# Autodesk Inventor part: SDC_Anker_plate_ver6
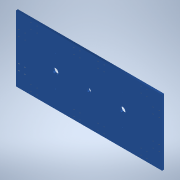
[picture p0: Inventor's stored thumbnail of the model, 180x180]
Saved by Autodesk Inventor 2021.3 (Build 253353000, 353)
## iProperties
Created: 2022-01
Part Number: SDC_Anker_plate_ver6
Material: アルミニウム 6061
Document SubType Name: Modeling
Designer: kengo
Density: 2.7 g/cm^3
Appearance: アルミニウム - フラット
Author: kengo
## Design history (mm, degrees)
sketch "スケッチ1"
  geometry: L1 (-589.671, 316.432)-(590.329, 316.432); L2 (590.329, 316.432)-(590.329, -283.568); L3 (590.329, -283.568)-(-589.671, -283.568); L4 (-589.671, -283.568)-(-589.671, 316.432); 1 further point
  constraints: 8 end point, 2 parallel, 1 horizontal, 1 perpendicular
  dimensions: "d0" = 600 distance of L3.end L1.start; "d1" = 1180 distance of L1.start L1.end
extrude "押し出し1" new body sketch "スケッチ1" distance "d2" = 15; taper "d3" = 0 deg
sketch "スケッチ4"
  geometry: L1 (-589.671, 316.432)-(-589.671, -283.568) reference; L2 (590.329, -283.568)-(590.329, 316.432) reference; L3 (-589.671, 261.432)-(590.329, 261.432); L4 (590.329, 261.432)-(590.329, -228.568); L5 (590.329, -228.568)-(-589.671, -228.568); L6 (-589.671, -228.568)-(-589.671, 261.432); L7 (590.329, 316.432)-(-589.671, 316.432) reference; L8 (-589.671, -283.568)-(590.329, -283.568) reference; L9 (-589.671, 316.432)-(590.329, 316.432); L10 (590.329, 316.432)-(590.329, -283.568); L11 (590.329, -283.568)-(-589.671, -283.568); L12 (-589.671, -283.568)-(-589.671, 316.432); 3 further points
  constraints: 16 end point, 4 parallel, 2 horizontal, 2 perpendicular, 2 point on line
  dimensions: "d58" = 490 distance between parallel lines of L5 L3; "d59" = 55 distance between parallel lines of L7 L3
extrude "押し出し2" cut sketch "スケッチ4" distance "d60" = 30; taper "d61" = 0 deg
sketch "スケッチ3" dims "d34" = 10, "d41" = 10
  geometry: L1 (-590.329, -283.568)-(-590.329, 316.432) reference; L2 (-590.329, 316.432)-(589.671, 316.432) reference; L3 (-590.329, 316.432)-(-180.344, 316.432); L4 (589.671, 261.432)-(-590.329, 261.432) reference; C1 r 3.324 at (-567.829, 228.932) reference; 25 further points
  constraints: 2 end point, 2 horizontal, 2 vertical, 1 point on line, 23 other
  dimensions: "d28" = 22.5 distance from line of L1 point (-567.829, 148.932); "d31" = 45 distance of point (-567.829, 148.932) point (-567.829, 103.932); "d38" = 45 distance of point (-567.829, 103.932) point (-522.829, 103.932); "d45" = 220 distance of point (-522.829, 148.932) point (-522.829, -71.068); "d48" = 1000 distance of point (-522.829, 148.932) point (477.171, 148.932); "d144" = 112.5 distance from line of L4 point (-567.829, 148.932)
hole "穴2" sketch "スケッチ3" diameter "d51" = 6.647; stored, may be unused: countersink angle "d55" = 90 deg, drill point angle "d57" = 118 deg; dims "d52" = 15, "d53" = 4, "d54" = 2, "d56" = 22.2
sketch "スケッチ5" dims "d83" = 10
  geometry: L1 (590.329, 261.432)-(-589.671, 261.432) reference; L2 (-589.671, 261.432)-(-589.671, -283.568) reference; 34 further points
  constraints: 2 horizontal, 1 vertical, 28 other
  dimensions: "d62" = 22.5 distance from line of L1 point (-387.171, 238.932); "d63" = 45 distance of point (-387.171, 193.932) point (-387.171, 238.932); "d64" = 45 distance of point (-342.171, 238.932) point (-342.171, 193.932); "d65" = 22.5 distance from line of L1 point (-342.171, 238.932); "d66" = 45 distance of point (-387.171, 193.932) point (-342.171, 193.932); "d69" = 45 distance of point (-387.171, 238.932) point (-342.171, 238.932); "d72" = 400 distance of point (-342.171, 238.932) point (-342.171, -161.068); "d75" = 320 distance of point (-342.171, 238.932) point (-22.171, 238.932); "d80" = 500 distance of point (-67.171, -161.068) point (432.829, -161.068); "d117" = 202.5 distance from line of L2 point (-387.171, 238.932); "d118" = 202.5 distance from line of L2 point (-387.171, 193.932)
hole "穴3" sketch "スケッチ5" diameter "d85" = 6.647; stored, may be unused: countersink angle "d89" = 90 deg, drill point angle "d91" = 118 deg; dims "d86" = 15, "d87" = 4, "d88" = 2, "d90" = 22.2
sketch "スケッチ7" dims "d101" = 10, "d108" = 10
  geometry: L1 (590.329, 261.432)-(-589.671, 261.432) reference; L2 (-589.671, 261.432)-(-589.671, -228.568) reference; L3 (-589.671, 261.432)-(-589.671, -228.568); C1 r 3.324 at (-342.171, 193.932) reference; 6 further points
  constraints: 2 end point, 1 collinear, 1 horizontal, 1 vertical, 3 other
  dimensions: "d94" = 130 distance from line of L1 point (-204.671, 131.432); "d95" = 137.5 horizontal distance of point (-204.671, 131.432) C1.centre; "d98" = 500 distance of point (-204.671, 131.432) point (295.329, 131.432); "d105" = 230 distance of point (295.329, 131.432) point (295.329, -98.568)
hole "穴4" sketch "スケッチ7" at (-204.671, 131.432), (295.329, 131.432), (295.329, -98.568), (-204.671, -98.568) diameter "d110" = 8; stored, may be unused: countersink angle "d114" = 90 deg, drill point angle "d116" = 118 deg; dims "d111" = 20, "d112" = 4, "d113" = 2, "d115" = 22.2
sketch "スケッチ8"
  geometry: L1 (-589.671, 261.432)-(590.329, 261.432) reference; L2 (590.329, -338.568)-(-589.671, -338.568); L3 (-499.671, 261.432)-(-589.671, 261.432); L4 (-589.671, 261.432)-(-589.671, -338.568); L5 (-589.671, -338.568)-(-499.671, -338.568); L6 (-499.671, -338.568)-(-499.671, 261.432); 3 further points
  constraints: 10 end point, 2 parallel, 1 horizontal, 1 perpendicular, 1 point on line
  dimensions: "d119" = 90 distance between parallel lines of L4 L6; "d142" = 600 distance of L5.end L3.start
extrude "押し出し4" cut sketch "スケッチ8" distance "d120" = 20; taper "d121" = 0 deg
sketch "スケッチ9"
  geometry: L1 (590.329, 261.432)-(-499.671, 261.432) reference; L2 (590.329, -228.568)-(590.329, 261.432) reference; 3 further points
  dimensions: "d122" = 245 distance from line of L1 point (45.329, 16.432); "d123" = 545 distance from line of L2 point (45.329, 16.432)
hole "穴5" sketch "スケッチ9" at (45.329, 16.432) diameter "d124" = 17.1; stored, may be unused: countersink angle "d128" = 90 deg, drill point angle "d130" = 118 deg; dims "d125" = 6, "d126" = 4, "d127" = 2, "d129" = 22.2
sketch "スケッチ10"
  geometry: L1 (-499.671, -228.568)-(590.329, -228.568) reference; C1 r 4 at (-204.671, 131.432) reference; C2 r 4 at (295.329, 131.432) reference; 3 further points
  dimensions: "d131" = 0 horizontal distance of C1.centre point (-204.671, 16.432); "d132" = 245 distance from line of L1 point (-204.671, 16.432); "d133" = 245 distance from line of L1 point (295.329, 16.432); "d134" = 0 horizontal distance of C2.centre point (295.329, 16.432)
hole "穴6" sketch "スケッチ10" at (-204.671, 16.432), (295.329, 16.432) diameter "d135" = 42; stored, may be unused: countersink angle "d139" = 90 deg, drill point angle "d141" = 118 deg; dims "d136" = 6, "d137" = 4, "d138" = 2, "d140" = 22.2
node "ソリッド1"
